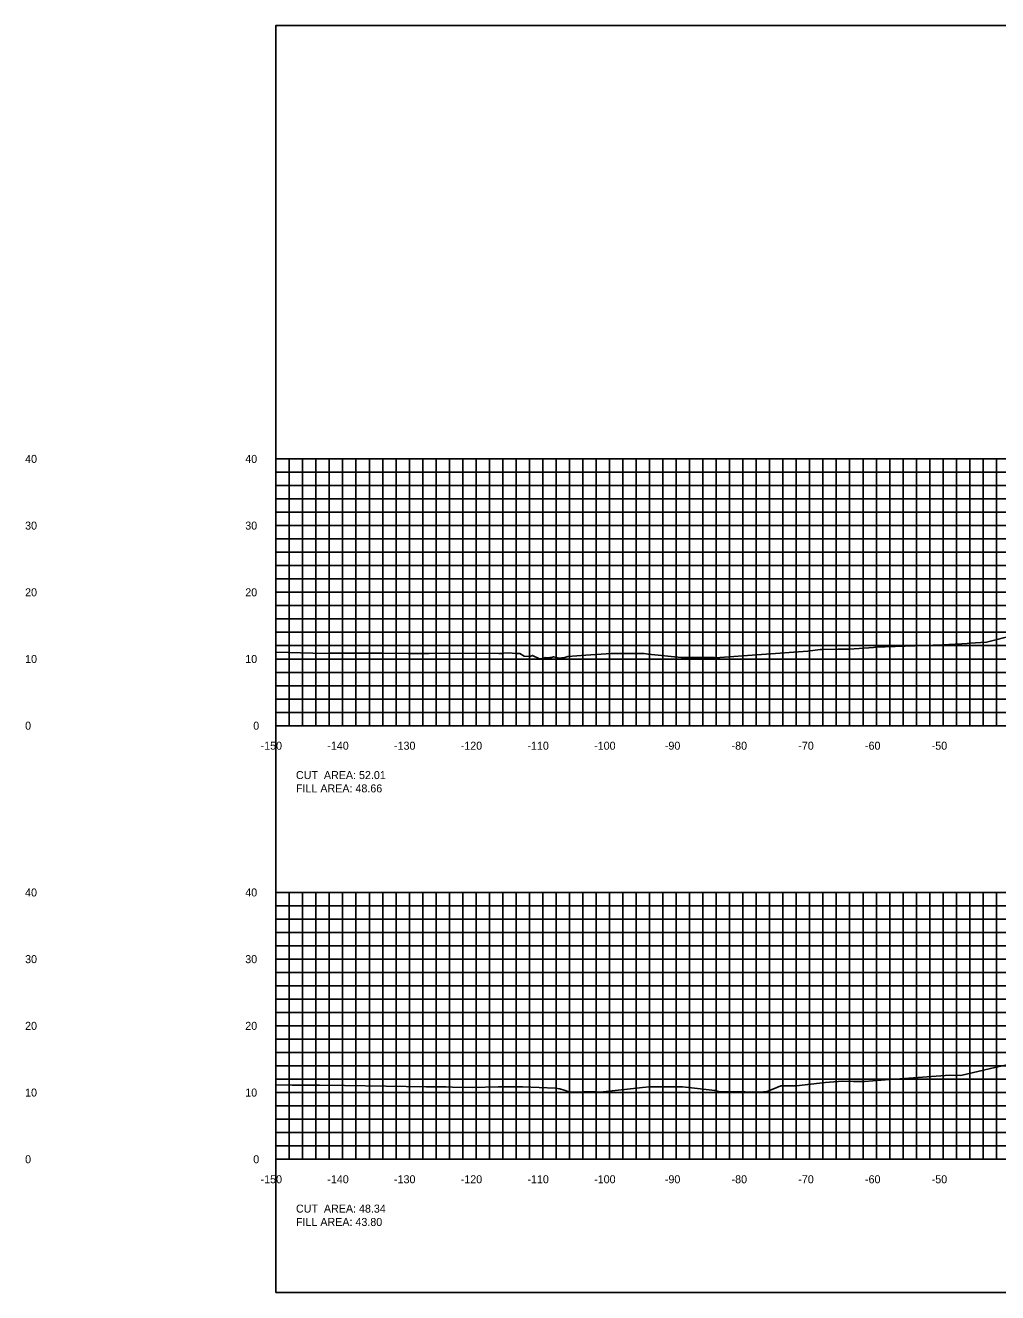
# Model space of a CAD drawing. Extents: x 1797652 to 1804159, y 242516 to 246906.
# Drawn here: x 1803816.9 to 1803962.7, y 242516 to 242706 of the extents above; entities that cross this region are included whole.
import ezdxf

# ---------------------------------------------------------------- set-up
doc = ezdxf.new("R2010")
doc.units = 0
for name, color, linetype in [('10', 7, 'Continuous'), ('31', 7, 'Continuous'), ('60', 7, 'Continuous'), ('Level 62', 7, 'Continuous'), ('M-ROADS', 7, 'Continuous')]:
    doc.layers.add(name, color=color, linetype=linetype)

msp = doc.modelspace()

# ---------------------------------------------------------------- linework, layer by layer
msp.add_lwpolyline([(1803854.49, 242516), (1804154.49, 242516), (1804154.49, 242706), (1803854.49, 242706)], close=True)
at = {"layer": '60'}
for p, q in [((1803854.43, 242641), (1803854.49, 242641)), ((1803854.49, 242601), (1803854.49, 242641)), ((1803854.43, 242631), (1803854.49, 242631)), ((1803854.43, 242621), (1803854.49, 242621)), ((1803854.43, 242611), (1803854.49, 242611)), ((1803854.43, 242601), (1803854.49, 242601)), ((1803854.49, 242601), (1804154.49, 242601)), ((1803854.49, 242600.94), (1803854.49, 242601)), ((1803864.49, 242600.94), (1803864.49, 242601)), ((1803874.49, 242600.94), (1803874.49, 242601)), ((1803884.49, 242600.94), (1803884.49, 242601)), ((1803894.49, 242600.94), (1803894.49, 242601)), ((1803904.49, 242600.94), (1803904.49, 242601)), ((1803914.49, 242600.94), (1803914.49, 242601)), ((1803924.49, 242600.94), (1803924.49, 242601)), ((1803934.49, 242600.94), (1803934.49, 242601)), ((1803944.49, 242600.94), (1803944.49, 242601)), ((1803954.49, 242600.94), (1803954.49, 242601)), ((1803854.43, 242576), (1803854.49, 242576)), ((1803854.49, 242536), (1803854.49, 242576)), ((1803854.43, 242566), (1803854.49, 242566)), ((1803854.43, 242556), (1803854.49, 242556)), ((1803854.43, 242546), (1803854.49, 242546)), ((1803854.43, 242536), (1803854.49, 242536)), ((1803854.49, 242536), (1804154.49, 242536)), ((1803854.49, 242535.94), (1803854.49, 242536)), ((1803864.49, 242535.94), (1803864.49, 242536)), ((1803874.49, 242535.94), (1803874.49, 242536)), ((1803884.49, 242535.94), (1803884.49, 242536)), ((1803894.49, 242535.94), (1803894.49, 242536)), ((1803904.49, 242535.94), (1803904.49, 242536)), ((1803914.49, 242535.94), (1803914.49, 242536)), ((1803924.49, 242535.94), (1803924.49, 242536)), ((1803934.49, 242535.94), (1803934.49, 242536)), ((1803944.49, 242535.94), (1803944.49, 242536)), ((1803954.49, 242535.94), (1803954.49, 242536))]:
    msp.add_line(p, q, dxfattribs=at)
at = {"layer": 'Level 62'}
for p, q in [((1803854.49, 242641), (1804154.49, 242641)), ((1803854.49, 242601), (1803854.49, 242641)), ((1803856.49, 242601), (1803856.49, 242641)), ((1803858.49, 242601), (1803858.49, 242641)), ((1803860.49, 242601), (1803860.49, 242641)), ((1803862.49, 242601), (1803862.49, 242641)), ((1803864.49, 242601), (1803864.49, 242641)), ((1803866.49, 242601), (1803866.49, 242641)), ((1803868.49, 242601), (1803868.49, 242641)), ((1803870.49, 242601), (1803870.49, 242641)), ((1803872.49, 242601), (1803872.49, 242641)), ((1803874.49, 242601), (1803874.49, 242641)), ((1803876.49, 242601), (1803876.49, 242641)), ((1803878.49, 242601), (1803878.49, 242641)), ((1803880.49, 242601), (1803880.49, 242641)), ((1803882.49, 242601), (1803882.49, 242641)), ((1803884.49, 242601), (1803884.49, 242641)), ((1803886.49, 242601), (1803886.49, 242641)), ((1803888.49, 242601), (1803888.49, 242641)), ((1803890.49, 242601), (1803890.49, 242641)), ((1803892.49, 242601), (1803892.49, 242641)), ((1803894.49, 242601), (1803894.49, 242641)), ((1803896.49, 242601), (1803896.49, 242641)), ((1803898.49, 242601), (1803898.49, 242641)), ((1803900.49, 242601), (1803900.49, 242641)), ((1803902.49, 242601), (1803902.49, 242641)), ((1803904.49, 242601), (1803904.49, 242641)), ((1803906.49, 242601), (1803906.49, 242641)), ((1803908.49, 242601), (1803908.49, 242641)), ((1803910.49, 242601), (1803910.49, 242641)), ((1803912.49, 242601), (1803912.49, 242641)), ((1803914.49, 242601), (1803914.49, 242641)), ((1803916.49, 242601), (1803916.49, 242641)), ((1803918.49, 242601), (1803918.49, 242641)), ((1803920.49, 242601), (1803920.49, 242641)), ((1803922.49, 242601), (1803922.49, 242641)), ((1803924.49, 242601), (1803924.49, 242641)), ((1803926.49, 242601), (1803926.49, 242641)), ((1803928.49, 242601), (1803928.49, 242641)), ((1803930.49, 242601), (1803930.49, 242641)), ((1803932.49, 242601), (1803932.49, 242641)), ((1803934.49, 242601), (1803934.49, 242641)), ((1803936.49, 242601), (1803936.49, 242641)), ((1803938.49, 242601), (1803938.49, 242641)), ((1803940.49, 242601), (1803940.49, 242641)), ((1803942.49, 242601), (1803942.49, 242641)), ((1803944.49, 242601), (1803944.49, 242641)), ((1803946.49, 242601), (1803946.49, 242641)), ((1803948.49, 242601), (1803948.49, 242641)), ((1803950.49, 242601), (1803950.49, 242641)), ((1803952.49, 242601), (1803952.49, 242641)), ((1803954.49, 242601), (1803954.49, 242641)), ((1803956.49, 242601), (1803956.49, 242641)), ((1803958.49, 242601), (1803958.49, 242641)), ((1803960.49, 242601), (1803960.49, 242641)), ((1803962.49, 242601), (1803962.49, 242641)), ((1803854.49, 242639), (1804154.49, 242639)), ((1803854.49, 242637), (1804154.49, 242637)), ((1803854.49, 242635), (1804154.49, 242635)), ((1803854.49, 242633), (1804154.49, 242633)), ((1803854.49, 242631), (1804154.49, 242631)), ((1803854.49, 242629), (1804154.49, 242629)), ((1803854.49, 242627), (1804154.49, 242627)), ((1803854.49, 242625), (1804154.49, 242625)), ((1803854.49, 242623), (1804154.49, 242623)), ((1803854.49, 242621), (1804154.49, 242621)), ((1803854.49, 242619), (1804154.49, 242619)), ((1803854.49, 242617), (1804154.49, 242617)), ((1803854.49, 242615), (1804154.49, 242615)), ((1803854.49, 242613), (1804154.49, 242613)), ((1803854.49, 242611), (1804154.49, 242611)), ((1803854.49, 242609), (1804154.49, 242609)), ((1803854.49, 242607), (1804154.49, 242607)), ((1803854.49, 242605), (1804154.49, 242605)), ((1803854.49, 242603), (1804154.49, 242603)), ((1803854.49, 242601), (1804154.49, 242601)), ((1803854.49, 242576), (1804154.49, 242576)), ((1803854.49, 242536), (1803854.49, 242576)), ((1803856.49, 242536), (1803856.49, 242576)), ((1803858.49, 242536), (1803858.49, 242576)), ((1803860.49, 242536), (1803860.49, 242576)), ((1803862.49, 242536), (1803862.49, 242576)), ((1803864.49, 242536), (1803864.49, 242576)), ((1803866.49, 242536), (1803866.49, 242576)), ((1803868.49, 242536), (1803868.49, 242576)), ((1803870.49, 242536), (1803870.49, 242576)), ((1803872.49, 242536), (1803872.49, 242576)), ((1803874.49, 242536), (1803874.49, 242576)), ((1803876.49, 242536), (1803876.49, 242576)), ((1803878.49, 242536), (1803878.49, 242576)), ((1803880.49, 242536), (1803880.49, 242576)), ((1803882.49, 242536), (1803882.49, 242576)), ((1803884.49, 242536), (1803884.49, 242576)), ((1803886.49, 242536), (1803886.49, 242576)), ((1803888.49, 242536), (1803888.49, 242576)), ((1803890.49, 242536), (1803890.49, 242576)), ((1803892.49, 242536), (1803892.49, 242576)), ((1803894.49, 242536), (1803894.49, 242576)), ((1803896.49, 242536), (1803896.49, 242576)), ((1803898.49, 242536), (1803898.49, 242576)), ((1803900.49, 242536), (1803900.49, 242576)), ((1803902.49, 242536), (1803902.49, 242576)), ((1803904.49, 242536), (1803904.49, 242576)), ((1803906.49, 242536), (1803906.49, 242576)), ((1803908.49, 242536), (1803908.49, 242576)), ((1803910.49, 242536), (1803910.49, 242576)), ((1803912.49, 242536), (1803912.49, 242576)), ((1803914.49, 242536), (1803914.49, 242576)), ((1803916.49, 242536), (1803916.49, 242576)), ((1803918.49, 242536), (1803918.49, 242576)), ((1803920.49, 242536), (1803920.49, 242576)), ((1803922.49, 242536), (1803922.49, 242576)), ((1803924.49, 242536), (1803924.49, 242576)), ((1803926.49, 242536), (1803926.49, 242576)), ((1803928.49, 242536), (1803928.49, 242576)), ((1803930.49, 242536), (1803930.49, 242576)), ((1803932.49, 242536), (1803932.49, 242576)), ((1803934.49, 242536), (1803934.49, 242576)), ((1803936.49, 242536), (1803936.49, 242576)), ((1803938.49, 242536), (1803938.49, 242576)), ((1803940.49, 242536), (1803940.49, 242576)), ((1803942.49, 242536), (1803942.49, 242576)), ((1803944.49, 242536), (1803944.49, 242576)), ((1803946.49, 242536), (1803946.49, 242576)), ((1803948.49, 242536), (1803948.49, 242576)), ((1803950.49, 242536), (1803950.49, 242576)), ((1803952.49, 242536), (1803952.49, 242576)), ((1803954.49, 242536), (1803954.49, 242576)), ((1803956.49, 242536), (1803956.49, 242576)), ((1803958.49, 242536), (1803958.49, 242576)), ((1803960.49, 242536), (1803960.49, 242576)), ((1803962.49, 242536), (1803962.49, 242576)), ((1803854.49, 242574), (1804154.49, 242574)), ((1803854.49, 242572), (1804154.49, 242572)), ((1803854.49, 242570), (1804154.49, 242570)), ((1803854.49, 242568), (1804154.49, 242568)), ((1803854.49, 242566), (1804154.49, 242566)), ((1803854.49, 242564), (1804154.49, 242564)), ((1803854.49, 242562), (1804154.49, 242562)), ((1803854.49, 242560), (1804154.49, 242560)), ((1803854.49, 242558), (1804154.49, 242558)), ((1803854.49, 242556), (1804154.49, 242556)), ((1803854.49, 242554), (1804154.49, 242554)), ((1803854.49, 242552), (1804154.49, 242552)), ((1803854.49, 242550), (1804154.49, 242550)), ((1803854.49, 242548), (1804154.49, 242548)), ((1803854.49, 242546), (1804154.49, 242546)), ((1803854.49, 242544), (1804154.49, 242544)), ((1803854.49, 242542), (1804154.49, 242542)), ((1803854.49, 242540), (1804154.49, 242540)), ((1803854.49, 242538), (1804154.49, 242538)), ((1803854.49, 242536), (1804154.49, 242536))]:
    msp.add_line(p, q, dxfattribs=at)
at = {"layer": 'M-ROADS'}
for points in [[(1803854.49, 242612.04), (1803861.89, 242611.84), (1803862.55, 242611.85), (1803864.49, 242611.86), (1803870.45, 242611.85), (1803874.33, 242611.83), (1803874.88, 242611.83), (1803875.74, 242611.83), (1803877.41, 242611.83), (1803879.91, 242611.86), (1803887.92, 242611.83), (1803888.38, 242611.82), (1803888.66, 242611.85), (1803889.36, 242611.9), (1803890.49, 242611.83), (1803890.57, 242611.8), (1803891.07, 242611.83), (1803891.68, 242611.42), (1803892.62, 242611.39), (1803892.97, 242611.54), (1803893.99, 242611.05), (1803894, 242611.05), (1803894, 242611.05), (1803894, 242611.05), (1803894.69, 242611.11), (1803894.86, 242611.23), (1803895.37, 242611.2), (1803895.59, 242611.25), (1803895.78, 242611.22), (1803896.1, 242611.34), (1803896.91, 242611.11), (1803897.79, 242611.25), (1803898.22, 242611.35), (1803900.96, 242611.58), (1803904.72, 242611.8), (1803906.25, 242611.81), (1803906.91, 242611.81), (1803907.03, 242611.81), (1803907.37, 242611.8), (1803907.56, 242611.84), (1803909.27, 242611.8), (1803909.68, 242611.8), (1803910.31, 242611.73), (1803915.22, 242611.21), (1803916.25, 242611.21), (1803917.4, 242611.21), (1803917.69, 242611.21), (1803917.76, 242611.21), (1803918.9, 242611.21), (1803920.19, 242611.21), (1803920.34, 242611.19), (1803934.23, 242612.19), (1803936.08, 242612.4), (1803936.45, 242612.41), (1803938.73, 242612.46), (1803939.79, 242612.46), (1803940.47, 242612.46), (1803944.08, 242612.74), (1803944.34, 242612.76), (1803950.27, 242612.97), (1803954.36, 242613.11), (1803957.3, 242613.29), (1803958.1, 242613.34), (1803958.51, 242613.37), (1803960.98, 242613.53), (1803965.14, 242614.55)], [(1803854.49, 242547.14), (1803856.92, 242547.12), (1803859.13, 242547.11), (1803861.01, 242547.1), (1803864.79, 242547.05), (1803871, 242546.96), (1803877.02, 242546.85), (1803879.38, 242546.86), (1803879.95, 242546.86), (1803880.95, 242546.82), (1803883.97, 242546.76), (1803887.81, 242546.85), (1803891.49, 242546.84), (1803896.4, 242546.67), (1803897.04, 242546.57), (1803897.71, 242546.35), (1803898.56, 242546.08), (1803900.38, 242546.12), (1803900.81, 242546.11), (1803901.12, 242546.09), (1803902.33, 242546.09), (1803902.96, 242546.08), (1803903.54, 242546.09), (1803909.45, 242546.74), (1803910.48, 242546.85), (1803911.17, 242546.85), (1803912.76, 242546.86), (1803913.03, 242546.87), (1803913.22, 242546.86), (1803914.32, 242546.86), (1803915.45, 242546.84), (1803917.69, 242546.63), (1803920.28, 242546.29), (1803921.01, 242546.12), (1803922.2, 242546.13), (1803923.06, 242546.1), (1803923.5, 242546.12), (1803924.11, 242546.09), (1803924.8, 242546.13), (1803925.71, 242546.07), (1803925.98, 242546.13), (1803926.99, 242546.04), (1803928.1, 242546.16), (1803930.19, 242547.03), (1803931.48, 242547.03), (1803932.51, 242547.03), (1803936.84, 242547.49), (1803939.43, 242547.7), (1803941.06, 242547.68), (1803942.09, 242547.68), (1803942.71, 242547.68), (1803946.47, 242547.95), (1803948, 242548.06), (1803955.53, 242548.63), (1803957.15, 242548.57), (1803962.44, 242549.83), (1803967.94, 242551)]]:
    msp.add_lwpolyline(points, dxfattribs=at)

# ---------------------------------------------------------------- texts
at = {"layer": '10'}
for s, p in [('-150', (1803852.19, 242597.4)), ('-140', (1803862.19, 242597.4)), ('-130', (1803872.19, 242597.4)), ('-120', (1803882.19, 242597.4)), ('-110', (1803892.19, 242597.4)), ('-100', (1803902.19, 242597.4)), ('-90', (1803912.79, 242597.4)), ('-80', (1803922.79, 242597.4)), ('-70', (1803932.79, 242597.4)), ('-60', (1803942.79, 242597.4)), ('-50', (1803952.79, 242597.4)), ('CUT  AREA: 52.01', (1803857.49, 242593)), ('FILL AREA: 48.66', (1803857.49, 242591)), ('-150', (1803852.19, 242532.4)), ('-140', (1803862.19, 242532.4)), ('-130', (1803872.19, 242532.4)), ('-120', (1803882.19, 242532.4)), ('-110', (1803892.19, 242532.4)), ('-100', (1803902.19, 242532.4)), ('-90', (1803912.79, 242532.4)), ('-80', (1803922.79, 242532.4)), ('-70', (1803932.79, 242532.4)), ('-60', (1803942.79, 242532.4)), ('-50', (1803952.79, 242532.4)), ('CUT  AREA: 48.34', (1803857.49, 242528)), ('FILL AREA: 43.80', (1803857.49, 242526))]:
    msp.add_text(s, height=1.2, dxfattribs=at).set_placement(p)
at = {"layer": '31'}
for s, p in [('40', (1803816.89, 242640.4)), ('40', (1803849.89, 242640.4)), ('30', (1803816.89, 242630.4)), ('30', (1803849.89, 242630.4)), ('20', (1803816.89, 242620.4)), ('20', (1803849.89, 242620.4)), ('10', (1803816.89, 242610.4)), ('10', (1803849.89, 242610.4)), ('0', (1803816.89, 242600.4)), ('0', (1803851.09, 242600.4)), ('40', (1803816.89, 242575.4)), ('40', (1803849.89, 242575.4)), ('30', (1803816.89, 242565.4)), ('30', (1803849.89, 242565.4)), ('20', (1803816.89, 242555.4)), ('20', (1803849.89, 242555.4)), ('10', (1803816.89, 242545.4)), ('10', (1803849.89, 242545.4)), ('0', (1803816.89, 242535.4)), ('0', (1803851.09, 242535.4))]:
    msp.add_text(s, height=1.2, dxfattribs=at).set_placement(p)
at = {"layer": '60'}
for p in [(1803854.49, 242601), (1803854.49, 242536)]:
    msp.add_text('-', height=0.0001, dxfattribs=at).set_placement(p)

doc.saveas('drawing.dxf')
